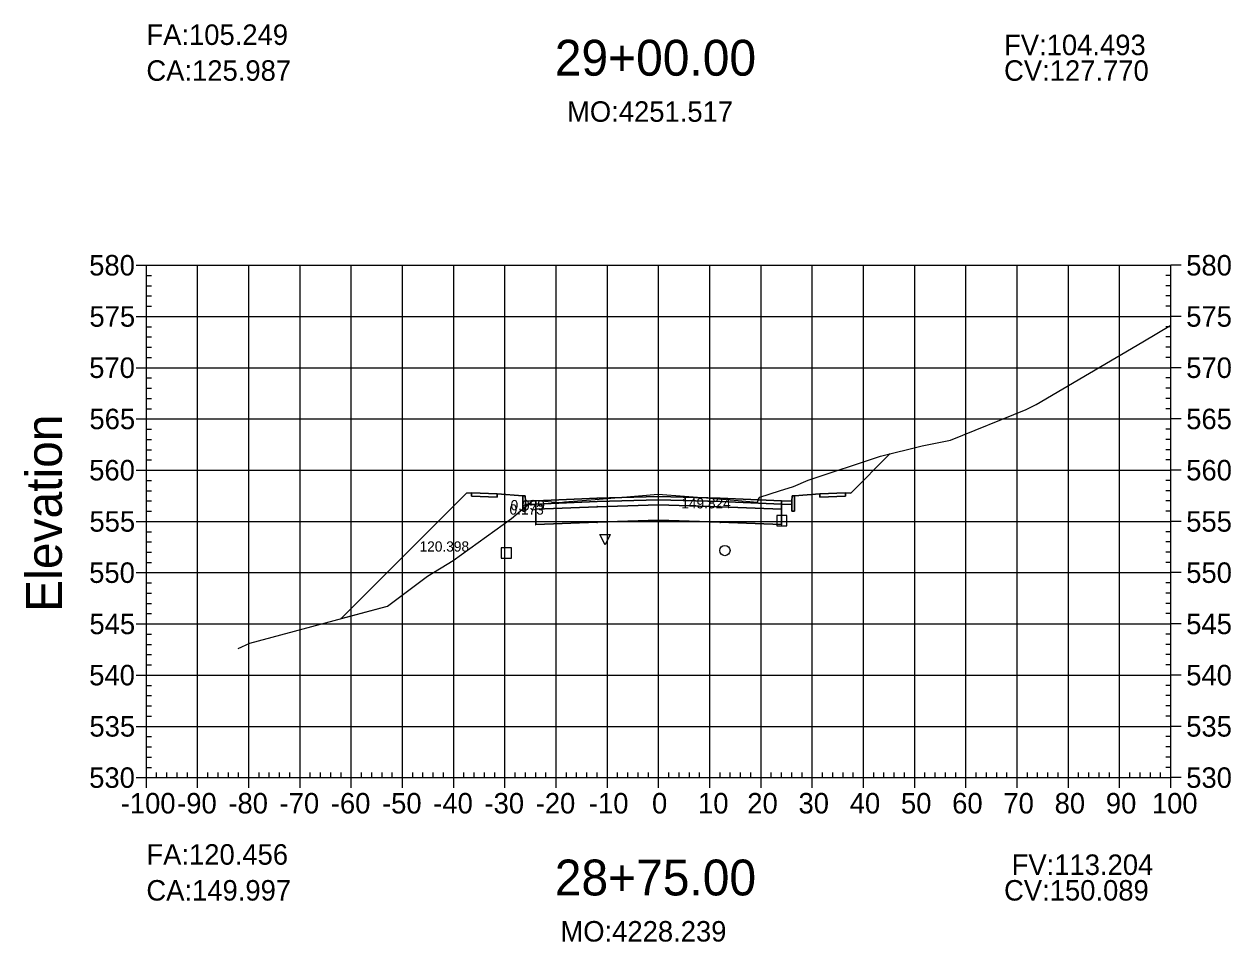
# Model space of a CAD drawing. Extents: x 704834 to 709892, y 372981 to 377533.
# Drawn here: x 706288 to 706523.6, y 374060.8 to 374239.9 of the extents above; entities that cross this region are included whole.
import ezdxf

# ---------------------------------------------------------------- set-up
doc = ezdxf.new("R2010")
doc.units = 0
for name, color, linetype in [('1', 7, 'Continuous'), ('10', 7, 'Continuous'), ('13', 7, 'Continuous'), ('14', 7, 'Continuous'), ('4', 7, 'Continuous'), ('57', 7, 'Continuous'), ('59', 7, 'Continuous'), ('60', 7, 'Continuous'), ('Default_Xsect', 7, 'Continuous'), ('Existing', 7, 'Continuous')]:
    doc.layers.add(name, color=color, linetype=linetype)

msp = doc.modelspace()

# ---------------------------------------------------------------- linework, layer by layer
for points in [[(706449.37, 374148.35), (706457.04, 374156.02)], [(706374.37, 374148.35), (706349.87, 374123.85)], [(706375.37, 374148.39), (706374.37, 374148.35)], [(706385.37, 374147.79), (706380.37, 374148.19)], [(706438.37, 374147.79), (706443.37, 374148.19)], [(706448.37, 374148.39), (706449.37, 374148.35)]]:
    msp.add_lwpolyline(points)
for points in [[(706380.37, 374148.19), (706375.37, 374148.39), (706375.37, 374147.73), (706380.37, 374147.53)], [(706385.87, 374146.79), (706385.79, 374147.79), (706385.37, 374147.79), (706385.37, 374144.79), (706385.87, 374144.79)], [(706411.87, 374147.05), (706423.87, 374146.69), (706435.87, 374146.21), (706435.87, 374146.87), (706423.87, 374147.35), (706411.87, 374147.71), (706399.87, 374147.35), (706387.87, 374146.87), (706387.87, 374146.21), (706399.87, 374146.69)], [(706411.87, 374146.05), (706423.87, 374145.69), (706435.87, 374145.21), (706435.87, 374146.21), (706423.87, 374146.69), (706411.87, 374147.05), (706399.87, 374146.69), (706387.87, 374146.21), (706387.87, 374145.21), (706399.87, 374145.69)], [(706411.82, 374147), (706411.92, 374147), (706411.92, 374147.1), (706411.82, 374147.1)], [(706437.87, 374144.79), (706438.37, 374144.79), (706438.37, 374147.79), (706437.96, 374147.79), (706437.87, 374146.79)], [(706443.37, 374147.53), (706448.37, 374147.73), (706448.37, 374148.39), (706443.37, 374148.19)], [(706387.87, 374146.87), (706385.87, 374146.79), (706385.87, 374146.13), (706387.87, 374146.21)], [(706387.82, 374145.16), (706387.92, 374145.16), (706387.92, 374145.26), (706387.82, 374145.26)], [(706411.87, 374143.05), (706423.87, 374142.69), (706435.87, 374142.21), (706435.87, 374145.21), (706423.87, 374145.69), (706411.87, 374146.05), (706399.87, 374145.69), (706387.87, 374145.21), (706387.87, 374142.21), (706399.87, 374142.69)], [(706399.82, 374145.64), (706399.92, 374145.64), (706399.92, 374145.74), (706399.82, 374145.74)], [(706411.82, 374146), (706411.92, 374146), (706411.92, 374146.1), (706411.82, 374146.1)], [(706423.82, 374145.64), (706423.92, 374145.64), (706423.92, 374145.74), (706423.82, 374145.74)], [(706435.82, 374145.16), (706435.92, 374145.16), (706435.92, 374145.26), (706435.82, 374145.26)], [(706435.87, 374146.21), (706437.87, 374146.13), (706437.87, 374146.79), (706435.87, 374146.87)], [(706387.82, 374142.16), (706387.92, 374142.16), (706387.92, 374142.26), (706387.82, 374142.26)], [(706399.82, 374142.64), (706399.92, 374142.64), (706399.92, 374142.74), (706399.82, 374142.74)], [(706411.82, 374143), (706411.92, 374143), (706411.92, 374143.1), (706411.82, 374143.1)], [(706423.82, 374142.64), (706423.92, 374142.64), (706423.92, 374142.74), (706423.82, 374142.74)], [(706435.82, 374142.16), (706435.92, 374142.16), (706435.92, 374142.26), (706435.82, 374142.26)]]:
    msp.add_lwpolyline(points, close=True)
at = {"layer": '1'}
for points in [[(706386.42, 374146.15), (706387.41, 374146.98), (706391.04, 374146.64), (706392.84, 374146.51), (706393.11, 374146.58), (706393.52, 374146.65), (706399.48, 374147.09), (706411.76, 374148.14), (706422.05, 374147.36), (706431.16, 374146.6), (706431.4, 374147.15), (706431.6, 374147.58), (706435.46, 374148.81), (706438.18, 374149.62), (706441.04, 374150.9), (706455.21, 374155.56), (706457.04, 374156.02), (706449.37, 374148.35), (706448.37, 374148.39), (706448.37, 374147.73), (706443.37, 374147.53), (706443.37, 374148.19), (706438.37, 374147.79), (706438.37, 374144.79), (706437.87, 374144.79), (706437.87, 374146.13), (706435.87, 374146.21), (706435.87, 374145.21), (706435.87, 374142.21), (706423.87, 374142.69), (706411.87, 374143.05), (706399.87, 374142.69), (706387.87, 374142.21), (706387.87, 374145.21), (706387.87, 374146.21)], [(706349.87, 374123.85), (706358.91, 374126.27), (706366.73, 374132.16), (706371.79, 374135.17), (706383.13, 374143.4), (706385.37, 374145.28), (706385.37, 374147.79), (706380.37, 374148.19), (706380.37, 374147.53), (706375.37, 374147.73), (706375.37, 374148.39), (706374.37, 374148.35)], [(706385.37, 374145.28), (706385.87, 374145.7), (706385.87, 374144.79), (706385.37, 374144.79)], [(706385.87, 374145.7), (706386.42, 374146.15), (706385.87, 374146.13)], [(706401.41, 374138.25), (706400.41, 374140.25), (706402.41, 374140.25)]]:
    msp.add_lwpolyline(points, close=True, dxfattribs=at)
at = {"layer": '10'}
msp.add_lwpolyline([(706381.13, 374135.68), (706383.13, 374135.68), (706383.13, 374137.68), (706381.13, 374137.68)], close=True, dxfattribs=at)
at = {"layer": '13'}
msp.add_circle((706424.81, 374137.13), 1, dxfattribs=at)
at = {"layer": '14'}
for points in [[(706457.04, 374156.02), (706457.04, 374156.07), (706457.04, 374156.02), (706456.99, 374156.02), (706457.04, 374156.02), (706457.04, 374155.97), (706457.04, 374156.02), (706457.09, 374156.02)], [(706387.87, 374146.87), (706387.87, 374146.92), (706387.87, 374146.87), (706387.82, 374146.87), (706387.87, 374146.87), (706387.87, 374146.82), (706387.87, 374146.87), (706387.92, 374146.87)], [(706399.87, 374147.35), (706399.87, 374147.4), (706399.87, 374147.35), (706399.82, 374147.35), (706399.87, 374147.35), (706399.87, 374147.3), (706399.87, 374147.35), (706399.92, 374147.35)], [(706411.87, 374147.71), (706411.87, 374147.76), (706411.87, 374147.71), (706411.82, 374147.71), (706411.87, 374147.71), (706411.87, 374147.66), (706411.87, 374147.71), (706411.92, 374147.71)], [(706423.87, 374147.35), (706423.87, 374147.4), (706423.87, 374147.35), (706423.82, 374147.35), (706423.87, 374147.35), (706423.87, 374147.3), (706423.87, 374147.35), (706423.92, 374147.35)], [(706435.87, 374146.87), (706435.87, 374146.92), (706435.87, 374146.87), (706435.82, 374146.87), (706435.87, 374146.87), (706435.87, 374146.82), (706435.87, 374146.87), (706435.92, 374146.87)], [(706349.87, 374123.85), (706349.87, 374123.9), (706349.87, 374123.85), (706349.82, 374123.85), (706349.87, 374123.85), (706349.87, 374123.8), (706349.87, 374123.85), (706349.92, 374123.85)]]:
    msp.add_lwpolyline(points, dxfattribs=at)
at = {"layer": '4'}
msp.add_lwpolyline([(706434.93, 374141.95), (706436.93, 374141.95), (706436.93, 374143.95), (706434.93, 374143.95)], close=True, dxfattribs=at)
at = {"layer": '57'}
for p, q in [((706309.87, 374192.82), (706311.87, 374192.82)), ((706311.87, 374192.82), (706511.87, 374192.82)), ((706311.87, 374092.82), (706311.87, 374192.82)), ((706311.87, 374092.82), (706311.87, 374192.82)), ((706321.87, 374092.82), (706321.87, 374192.82)), ((706331.87, 374092.82), (706331.87, 374192.82)), ((706341.87, 374092.82), (706341.87, 374192.82)), ((706351.87, 374092.82), (706351.87, 374192.82)), ((706361.87, 374092.82), (706361.87, 374192.82)), ((706371.87, 374092.82), (706371.87, 374192.82)), ((706381.87, 374092.82), (706381.87, 374192.82)), ((706391.87, 374092.82), (706391.87, 374192.82)), ((706401.87, 374092.82), (706401.87, 374192.82)), ((706411.87, 374092.82), (706411.87, 374192.82)), ((706421.87, 374092.82), (706421.87, 374192.82)), ((706431.87, 374092.82), (706431.87, 374192.82)), ((706441.87, 374092.82), (706441.87, 374192.82)), ((706451.87, 374092.82), (706451.87, 374192.82)), ((706461.87, 374092.82), (706461.87, 374192.82)), ((706471.87, 374092.82), (706471.87, 374192.82)), ((706481.87, 374092.82), (706481.87, 374192.82)), ((706491.87, 374092.82), (706491.87, 374192.82)), ((706501.87, 374092.82), (706501.87, 374192.82)), ((706511.87, 374092.82), (706511.87, 374192.82)), ((706511.87, 374092.82), (706511.87, 374192.82)), ((706513.87, 374192.82), (706511.87, 374192.82)), ((706311.87, 374190.82), (706312.87, 374190.82)), ((706511.87, 374190.82), (706510.87, 374190.82)), ((706311.87, 374188.82), (706312.87, 374188.82)), ((706511.87, 374188.82), (706510.87, 374188.82)), ((706311.87, 374186.82), (706312.87, 374186.82)), ((706311.87, 374184.82), (706312.87, 374184.82)), ((706511.87, 374186.82), (706510.87, 374186.82)), ((706511.87, 374184.82), (706510.87, 374184.82)), ((706309.87, 374182.82), (706311.87, 374182.82)), ((706311.87, 374182.82), (706511.87, 374182.82)), ((706513.87, 374182.82), (706511.87, 374182.82)), ((706311.87, 374180.82), (706312.87, 374180.82)), ((706511.87, 374180.82), (706510.87, 374180.82)), ((706311.87, 374178.82), (706312.87, 374178.82)), ((706511.87, 374178.82), (706510.87, 374178.82)), ((706311.87, 374176.82), (706312.87, 374176.82)), ((706511.87, 374176.82), (706510.87, 374176.82)), ((706311.87, 374174.82), (706312.87, 374174.82)), ((706511.87, 374174.82), (706510.87, 374174.82)), ((706309.87, 374172.82), (706311.87, 374172.82)), ((706311.87, 374172.82), (706511.87, 374172.82)), ((706311.87, 374170.82), (706312.87, 374170.82)), ((706511.87, 374170.82), (706510.87, 374170.82)), ((706513.87, 374172.82), (706511.87, 374172.82)), ((706311.87, 374168.82), (706312.87, 374168.82)), ((706511.87, 374168.82), (706510.87, 374168.82)), ((706311.87, 374166.82), (706312.87, 374166.82)), ((706511.87, 374166.82), (706510.87, 374166.82)), ((706311.87, 374164.82), (706312.87, 374164.82)), ((706511.87, 374164.82), (706510.87, 374164.82)), ((706309.87, 374162.82), (706311.87, 374162.82)), ((706311.87, 374162.82), (706511.87, 374162.82)), ((706513.87, 374162.82), (706511.87, 374162.82)), ((706311.87, 374160.82), (706312.87, 374160.82)), ((706311.87, 374158.82), (706312.87, 374158.82)), ((706511.87, 374160.82), (706510.87, 374160.82)), ((706511.87, 374158.82), (706510.87, 374158.82)), ((706311.87, 374156.82), (706312.87, 374156.82)), ((706511.87, 374156.82), (706510.87, 374156.82)), ((706311.87, 374154.82), (706312.87, 374154.82)), ((706511.87, 374154.82), (706510.87, 374154.82)), ((706309.87, 374152.82), (706311.87, 374152.82)), ((706311.87, 374152.82), (706511.87, 374152.82)), ((706513.87, 374152.82), (706511.87, 374152.82)), ((706311.87, 374150.82), (706312.87, 374150.82)), ((706511.87, 374150.82), (706510.87, 374150.82)), ((706311.87, 374148.82), (706312.87, 374148.82)), ((706511.87, 374148.82), (706510.87, 374148.82)), ((706311.87, 374146.82), (706312.87, 374146.82)), ((706311.87, 374144.82), (706312.87, 374144.82)), ((706511.87, 374146.82), (706510.87, 374146.82)), ((706511.87, 374144.82), (706510.87, 374144.82)), ((706309.87, 374142.82), (706311.87, 374142.82)), ((706311.87, 374142.82), (706511.87, 374142.82)), ((706513.87, 374142.82), (706511.87, 374142.82)), ((706311.87, 374140.82), (706312.87, 374140.82)), ((706511.87, 374140.82), (706510.87, 374140.82)), ((706311.87, 374138.82), (706312.87, 374138.82)), ((706511.87, 374138.82), (706510.87, 374138.82)), ((706311.87, 374136.82), (706312.87, 374136.82)), ((706511.87, 374136.82), (706510.87, 374136.82)), ((706309.87, 374132.82), (706311.87, 374132.82)), ((706311.87, 374134.82), (706312.87, 374134.82)), ((706311.87, 374132.82), (706511.87, 374132.82)), ((706511.87, 374134.82), (706510.87, 374134.82)), ((706513.87, 374132.82), (706511.87, 374132.82)), ((706311.87, 374130.82), (706312.87, 374130.82)), ((706511.87, 374130.82), (706510.87, 374130.82)), ((706311.87, 374128.82), (706312.87, 374128.82)), ((706511.87, 374128.82), (706510.87, 374128.82)), ((706311.87, 374126.82), (706312.87, 374126.82)), ((706511.87, 374126.82), (706510.87, 374126.82)), ((706311.87, 374124.82), (706312.87, 374124.82)), ((706511.87, 374124.82), (706510.87, 374124.82)), ((706309.87, 374122.82), (706311.87, 374122.82)), ((706311.87, 374122.82), (706511.87, 374122.82)), ((706513.87, 374122.82), (706511.87, 374122.82)), ((706311.87, 374120.82), (706312.87, 374120.82)), ((706311.87, 374118.82), (706312.87, 374118.82)), ((706511.87, 374120.82), (706510.87, 374120.82)), ((706511.87, 374118.82), (706510.87, 374118.82)), ((706311.87, 374116.82), (706312.87, 374116.82)), ((706511.87, 374116.82), (706510.87, 374116.82)), ((706311.87, 374114.82), (706312.87, 374114.82)), ((706511.87, 374114.82), (706510.87, 374114.82)), ((706309.87, 374112.82), (706311.87, 374112.82)), ((706311.87, 374112.82), (706511.87, 374112.82)), ((706513.87, 374112.82), (706511.87, 374112.82)), ((706311.87, 374110.82), (706312.87, 374110.82)), ((706511.87, 374110.82), (706510.87, 374110.82)), ((706311.87, 374108.82), (706312.87, 374108.82)), ((706511.87, 374108.82), (706510.87, 374108.82)), ((706311.87, 374106.82), (706312.87, 374106.82)), ((706311.87, 374104.82), (706312.87, 374104.82)), ((706511.87, 374106.82), (706510.87, 374106.82)), ((706511.87, 374104.82), (706510.87, 374104.82)), ((706309.87, 374102.82), (706311.87, 374102.82)), ((706311.87, 374102.82), (706511.87, 374102.82)), ((706513.87, 374102.82), (706511.87, 374102.82)), ((706311.87, 374100.82), (706312.87, 374100.82)), ((706511.87, 374100.82), (706510.87, 374100.82)), ((706311.87, 374098.82), (706312.87, 374098.82)), ((706511.87, 374098.82), (706510.87, 374098.82)), ((706311.87, 374096.82), (706312.87, 374096.82)), ((706511.87, 374096.82), (706510.87, 374096.82)), ((706309.87, 374092.82), (706311.87, 374092.82)), ((706311.87, 374094.82), (706312.87, 374094.82)), ((706311.87, 374092.82), (706511.87, 374092.82)), ((706311.87, 374092.82), (706511.87, 374092.82)), ((706311.87, 374090.82), (706311.87, 374092.82)), ((706313.87, 374092.82), (706313.87, 374093.82)), ((706315.87, 374092.82), (706315.87, 374093.82)), ((706317.87, 374092.82), (706317.87, 374093.82)), ((706319.87, 374092.82), (706319.87, 374093.82)), ((706321.87, 374090.82), (706321.87, 374092.82)), ((706323.87, 374092.82), (706323.87, 374093.82)), ((706325.87, 374092.82), (706325.87, 374093.82)), ((706327.87, 374092.82), (706327.87, 374093.82)), ((706329.87, 374092.82), (706329.87, 374093.82)), ((706331.87, 374090.82), (706331.87, 374092.82)), ((706333.87, 374092.82), (706333.87, 374093.82)), ((706335.87, 374092.82), (706335.87, 374093.82)), ((706337.87, 374092.82), (706337.87, 374093.82)), ((706339.87, 374092.82), (706339.87, 374093.82)), ((706341.87, 374090.82), (706341.87, 374092.82)), ((706343.87, 374092.82), (706343.87, 374093.82)), ((706345.87, 374092.82), (706345.87, 374093.82)), ((706347.87, 374092.82), (706347.87, 374093.82)), ((706349.87, 374092.82), (706349.87, 374093.82)), ((706351.87, 374090.82), (706351.87, 374092.82)), ((706353.87, 374092.82), (706353.87, 374093.82)), ((706355.87, 374092.82), (706355.87, 374093.82)), ((706357.87, 374092.82), (706357.87, 374093.82)), ((706359.87, 374092.82), (706359.87, 374093.82)), ((706361.87, 374090.82), (706361.87, 374092.82)), ((706363.87, 374092.82), (706363.87, 374093.82)), ((706365.87, 374092.82), (706365.87, 374093.82)), ((706367.87, 374092.82), (706367.87, 374093.82)), ((706369.87, 374092.82), (706369.87, 374093.82)), ((706371.87, 374090.82), (706371.87, 374092.82)), ((706373.87, 374092.82), (706373.87, 374093.82)), ((706375.87, 374092.82), (706375.87, 374093.82)), ((706377.87, 374092.82), (706377.87, 374093.82)), ((706379.87, 374092.82), (706379.87, 374093.82)), ((706381.87, 374090.82), (706381.87, 374092.82)), ((706383.87, 374092.82), (706383.87, 374093.82)), ((706385.87, 374092.82), (706385.87, 374093.82)), ((706387.87, 374092.82), (706387.87, 374093.82)), ((706389.87, 374092.82), (706389.87, 374093.82)), ((706391.87, 374090.82), (706391.87, 374092.82)), ((706393.87, 374092.82), (706393.87, 374093.82)), ((706395.87, 374092.82), (706395.87, 374093.82)), ((706397.87, 374092.82), (706397.87, 374093.82)), ((706399.87, 374092.82), (706399.87, 374093.82)), ((706401.87, 374090.82), (706401.87, 374092.82)), ((706403.87, 374092.82), (706403.87, 374093.82)), ((706405.87, 374092.82), (706405.87, 374093.82)), ((706407.87, 374092.82), (706407.87, 374093.82)), ((706409.87, 374092.82), (706409.87, 374093.82)), ((706411.87, 374090.82), (706411.87, 374092.82)), ((706413.87, 374092.82), (706413.87, 374093.82)), ((706415.87, 374092.82), (706415.87, 374093.82)), ((706417.87, 374092.82), (706417.87, 374093.82)), ((706419.87, 374092.82), (706419.87, 374093.82)), ((706421.87, 374090.82), (706421.87, 374092.82)), ((706423.87, 374092.82), (706423.87, 374093.82)), ((706425.87, 374092.82), (706425.87, 374093.82)), ((706427.87, 374092.82), (706427.87, 374093.82)), ((706429.87, 374092.82), (706429.87, 374093.82)), ((706431.87, 374090.82), (706431.87, 374092.82)), ((706433.87, 374092.82), (706433.87, 374093.82)), ((706435.87, 374092.82), (706435.87, 374093.82)), ((706437.87, 374092.82), (706437.87, 374093.82)), ((706439.87, 374092.82), (706439.87, 374093.82)), ((706441.87, 374090.82), (706441.87, 374092.82)), ((706443.87, 374092.82), (706443.87, 374093.82)), ((706445.87, 374092.82), (706445.87, 374093.82)), ((706447.87, 374092.82), (706447.87, 374093.82)), ((706449.87, 374092.82), (706449.87, 374093.82)), ((706451.87, 374090.82), (706451.87, 374092.82)), ((706453.87, 374092.82), (706453.87, 374093.82)), ((706455.87, 374092.82), (706455.87, 374093.82)), ((706457.87, 374092.82), (706457.87, 374093.82)), ((706459.87, 374092.82), (706459.87, 374093.82)), ((706461.87, 374090.82), (706461.87, 374092.82)), ((706463.87, 374092.82), (706463.87, 374093.82)), ((706465.87, 374092.82), (706465.87, 374093.82)), ((706467.87, 374092.82), (706467.87, 374093.82)), ((706469.87, 374092.82), (706469.87, 374093.82)), ((706471.87, 374090.82), (706471.87, 374092.82)), ((706473.87, 374092.82), (706473.87, 374093.82)), ((706475.87, 374092.82), (706475.87, 374093.82)), ((706477.87, 374092.82), (706477.87, 374093.82)), ((706479.87, 374092.82), (706479.87, 374093.82)), ((706481.87, 374090.82), (706481.87, 374092.82)), ((706483.87, 374092.82), (706483.87, 374093.82)), ((706485.87, 374092.82), (706485.87, 374093.82)), ((706487.87, 374092.82), (706487.87, 374093.82)), ((706489.87, 374092.82), (706489.87, 374093.82)), ((706491.87, 374090.82), (706491.87, 374092.82)), ((706493.87, 374092.82), (706493.87, 374093.82)), ((706495.87, 374092.82), (706495.87, 374093.82)), ((706497.87, 374092.82), (706497.87, 374093.82)), ((706499.87, 374092.82), (706499.87, 374093.82)), ((706501.87, 374090.82), (706501.87, 374092.82)), ((706503.87, 374092.82), (706503.87, 374093.82)), ((706505.87, 374092.82), (706505.87, 374093.82)), ((706507.87, 374092.82), (706507.87, 374093.82)), ((706509.87, 374092.82), (706509.87, 374093.82)), ((706511.87, 374094.82), (706510.87, 374094.82)), ((706511.87, 374090.82), (706511.87, 374092.82)), ((706513.87, 374092.82), (706511.87, 374092.82))]:
    msp.add_line(p, q, dxfattribs=at)
at = {"layer": 'Default_Xsect'}
msp.add_lwpolyline([(706349.87, 374123.85), (706374.37, 374148.35), (706375.37, 374148.39), (706380.37, 374148.19), (706385.37, 374147.79), (706385.79, 374147.79), (706385.87, 374146.79), (706387.87, 374146.87), (706399.87, 374147.35), (706411.87, 374147.71), (706423.87, 374147.35), (706435.87, 374146.87), (706437.87, 374146.79), (706437.96, 374147.79), (706438.37, 374147.79), (706443.37, 374148.19), (706448.37, 374148.39), (706449.37, 374148.35), (706457.04, 374156.02)], dxfattribs=at)
at = {"layer": 'Existing'}
msp.add_lwpolyline([(706329.8, 374118.05), (706332.04, 374119.07), (706358.91, 374126.27), (706366.73, 374132.16), (706371.79, 374135.17), (706383.13, 374143.4), (706387.41, 374146.98), (706391.04, 374146.64), (706392.84, 374146.51), (706393.11, 374146.58), (706393.52, 374146.65), (706399.48, 374147.09), (706411.76, 374148.14), (706422.05, 374147.36), (706431.16, 374146.6), (706431.4, 374147.15), (706431.6, 374147.58), (706435.46, 374148.81), (706438.18, 374149.62), (706441.04, 374150.9), (706455.21, 374155.56), (706463.32, 374157.6), (706468.84, 374158.66), (706483.64, 374164.64), (706485.59, 374165.66), (706506.42, 374177.9), (706511.87, 374181.13)], dxfattribs=at)

# ---------------------------------------------------------------- texts
for s, p in [('CA:125.987', (706311.87, 374228.82)), ('CV:127.770', (706479.31, 374228.82)), ('CA:149.997', (706311.87, 374068.82)), ('CV:150.089', (706479.31, 374068.82))]:
    msp.add_text(s, height=4).set_placement(p)
at = {"layer": '1'}
for s, p in [('29+00.00', (706391.6, 374229.82)), ('28+75.00', (706391.6, 374069.82))]:
    msp.add_text(s, height=7, dxfattribs=at).set_placement(p)
at = {"layer": '14'}
for p in [(706375.34, 374148.34), (706375.34, 374147.68), (706380.34, 374147.48), (706443.34, 374147.48), (706448.34, 374148.34), (706448.34, 374147.68)]:
    msp.add_text('+', height=0.1, dxfattribs=at).set_placement(p)
at = {"layer": '57'}
for s, p in [('580', (706300.7, 374190.82)), ('580', (706514.87, 374190.82)), ('575', (706300.75, 374180.82)), ('575', (706514.87, 374180.82)), ('570', (706300.7, 374170.82)), ('570', (706514.87, 374170.82)), ('565', (706300.75, 374160.82)), ('565', (706514.87, 374160.82)), ('560', (706300.7, 374150.82)), ('560', (706514.87, 374150.82)), ('555', (706300.75, 374140.82)), ('555', (706514.87, 374140.82)), ('550', (706300.7, 374130.82)), ('550', (706514.87, 374130.82)), ('545', (706300.75, 374120.82)), ('545', (706514.87, 374120.82)), ('540', (706300.7, 374110.82)), ('540', (706514.87, 374110.82)), ('535', (706300.75, 374100.82)), ('535', (706514.87, 374100.82)), ('530', (706300.7, 374090.82)), ('530', (706514.87, 374090.82)), ('-100', (706306.86, 374085.82)), ('-90', (706317.87, 374085.82)), ('-80', (706327.87, 374085.82)), ('-70', (706337.87, 374085.82)), ('-60', (706347.87, 374085.82)), ('-50', (706357.87, 374085.82)), ('-40', (706367.87, 374085.82)), ('-30', (706377.87, 374085.82)), ('-20', (706387.87, 374085.82)), ('-10', (706398.26, 374085.82)), ('0', (706410.58, 374085.82)), ('10', (706419.57, 374085.82)), ('20', (706429.18, 374085.82)), ('30', (706439.18, 374085.82)), ('40', (706449.18, 374085.82)), ('50', (706459.18, 374085.82)), ('60', (706469.18, 374085.82)), ('70', (706479.18, 374085.82)), ('80', (706489.18, 374085.82)), ('90', (706499.18, 374085.82)), ('100', (706508.17, 374085.82))]:
    msp.add_text(s, height=4, dxfattribs=at).set_placement(p)
at = {"layer": '59'}
for s, height, p in [('FA:105.249', 4, (706311.87, 374235.82)), ('FV:104.493', 4, (706479.31, 374233.82)), ('MO:4251.517', 4, (706393.99, 374220.82)), ('0.059', 2, (706382.97, 374144.99)), ('149.824', 2, (706416.29, 374145.36)), ('0.173', 2, (706382.76, 374144.15)), ('120.398', 2, (706365.2, 374136.93)), ('FA:120.456', 4, (706311.87, 374075.82)), ('FV:113.204', 4, (706480.79, 374073.82)), ('MO:4228.239', 4, (706392.7, 374060.82))]:
    msp.add_text(s, height=height, dxfattribs=at).set_placement(p)
at = {"layer": '60'}
msp.add_text('Elevation', height=7, rotation=90, dxfattribs=at).set_placement((706295.37, 374125.18))

doc.saveas('drawing.dxf')
